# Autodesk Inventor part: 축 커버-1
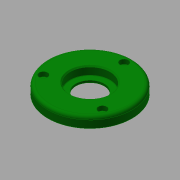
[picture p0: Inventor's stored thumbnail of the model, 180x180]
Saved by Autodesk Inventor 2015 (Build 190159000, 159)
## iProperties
Created: 2015-10
Part Number: 축 커버-1
Document SubType Name: Modeling
Designer: mdu
Density: 1 g/cm^3
Material: 강철, 연강
Appearance: 진녹색
Author: mdu
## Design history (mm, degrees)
sketch "스케치1"
  geometry: C1 r 40 at (0, 0) reference; C2 r 26 at (0, 0) reference; 1 further point
  node "참조1"
  node "참조2"
extrude "돌출1" new body sketch "스케치1" distance "d0" = 10; taper "d1" = 0 deg
extrude "돌출2" join sketch "스케치1" distance "d2" = 3; taper "d3" = 0 deg
hole "구멍1" diameter "d6" = 27; stored, may be unused: countersink angle "d10" = 90 deg, drill point angle "d12" = 118 deg; dims "d4" = 10, "d5" = 10, "d7" = 6, "d8" = 38, "d9" = 8, "d11" = 8
sketch "스케치2"
  geometry: C1 r 20 at (0, 0); 1 further point
  constraints: 1 centre point, 1 coincident
  dimensions: "d13" = 40 diameter of C1
extrude "돌출3" cut sketch "스케치2" distance "d14" = 3; taper "d15" = 0 deg
sketch "스케치3"
  geometry: C1 r 1.621 at (0, 32.5) reference; 1 further point
hole "구멍2" sketch "스케치3" at (0, 32.5) diameter "d16" = 4.5; stored, may be unused: countersink angle "d20" = 90 deg, drill point angle "d22" = 118 deg; dims "d17" = 6, "d18" = 8, "d19" = 4.4, "d21" = 8
fillet "모깎기1" dims "d26" = 3, "d27" = 0.3
chamfer "모따기1" distance "d28" = 1; stored, may be unused: second distance "d29" = 2, angle "d30" = 45 deg
node "솔리드1"
pattern_circular "원형 패턴1" dims angle "d24" = 360 deg
node "참조3"
